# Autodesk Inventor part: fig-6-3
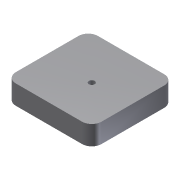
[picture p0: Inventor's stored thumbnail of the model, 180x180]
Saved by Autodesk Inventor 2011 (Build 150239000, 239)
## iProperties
Created: 2004-05
Part Number: fig-6-3
Document SubType Name: Modeling
Designer: CADCIM Technologies
Manufacturer: Standard
Standards Organization: Custom
Density: 1 g/cm^3
Author: CADCIM Technologies
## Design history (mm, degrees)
sketch "Sketch1"
  geometry: L1 (0, 0)-(44.293, 0); L2 (44.293, 0)-(44.293, 42.442); L3 (44.293, 42.442)-(0, 42.442); L4 (0, 42.442)-(0, 0)
  constraints: 8 end point, 2 parallel, 1 horizontal, 1 perpendicular
extrude "Extrusion1" new body sketch "Sketch1" distance "d0" = 10; taper "d1" = 0 deg
fillet "Fillet1" dims "d2" = 5
hole "Hole1" diameter "d6" = 3; stored, may be unused: countersink angle "d10" = 90 deg, drill point angle "d12" = 118 deg; dims "d4" = 20, "d5" = 20, "d7" = 6, "d8" = 4, "d9" = 2, "d11" = 8
body "Solid1"
